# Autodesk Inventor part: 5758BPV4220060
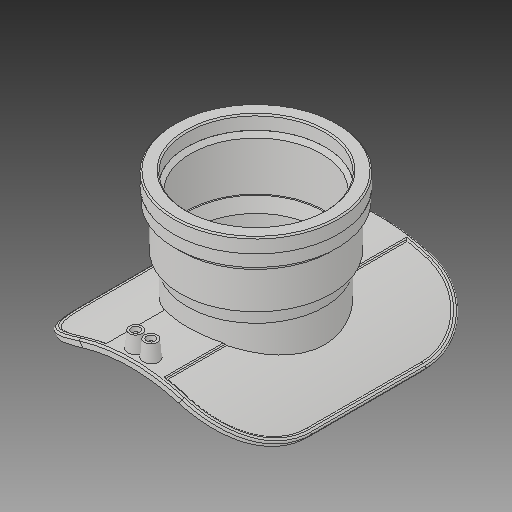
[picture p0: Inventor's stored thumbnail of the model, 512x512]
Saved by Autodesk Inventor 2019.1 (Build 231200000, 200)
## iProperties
Created: 2017-08
Part Number: 5758BPV4220060
Material: Generic
Description: PLASSON WASTEWATER SADDLE TEE 90 14''DIPS x 6''PSM for PVC
Document SubType Name: Modeling
Designer: Кирилл
Density: 1 g/cm^3
Appearance: Default
Author: Кирилл
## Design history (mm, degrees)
derived "5758BP.ipt"
feature "Solid1::5758BP.ipt"
feature "Solid2::5758BP.ipt"
feature "Solid3::5758BP.ipt"
tag "TaggingFeature1"
body "Solid1"
other parameters: "d0" = 386.8, "d1" = 261.62, "d2" = 402.272, "d3" = 289.56, "d4" = 0, "d5" = 78.486, "d6" = 6.364, "d7" = 20 deg, "d8" = 10 deg, "d10" = 0, "d11" = 251.42, "d38" = 1.934, "d40" = 219.4, "d41" = 15, "d42" = 130.302, "d43" = 17.501, "d44" = 8.7505, "d46" = 5 deg, "d47" = 4, "d49" = 4, "d51" = 14, "d52" = 0, "d53" = 3, "d54" = 0, "d56" = 159.1, "d57" = 0.5, "d58" = 80.01, "d59" = 16.002, "d60" = 5.6007, "d61" = 40 deg, "d62" = 151.145, "d63" = 155.918, "d64" = 143.19, "d65" = 155 deg, "d66" = 124.968, "d67" = 189.992, "d68" = 188.09208, "d69" = 45 deg, "d70" = 174.546, "d72" = 7.723, "d75" = 0, "d77" = 0, "d78" = 1.591, "d81" = 37.4904, "d_" = 386.8, "B_" = 261.62, "H_" = 124.968, "L_" = 289.56, "d_1" = 159.1, "D_" = 189.992, "L_1" = 80.01, "d71" = 7.723
